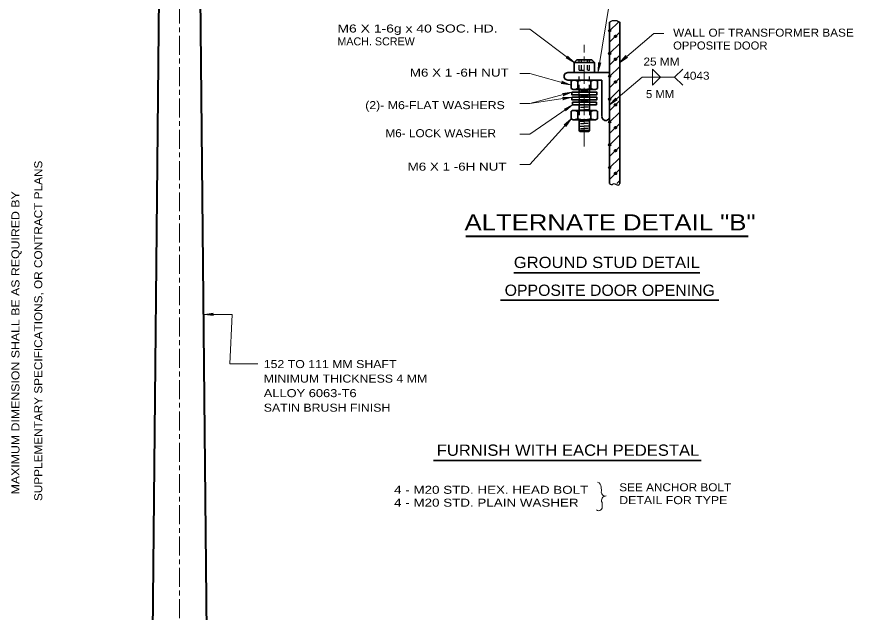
# Model space of a CAD drawing. Extents: x 312583 to 312854, y 144419 to 144597.
# Drawn here: x 312624.6 to 312704, y 144475.1 to 144531.6 of the extents above; entities that cross this region are included whole.
import ezdxf
from ezdxf.enums import TextEntityAlignment as Align

# ---------------------------------------------------------------- set-up
doc = ezdxf.new("R2010")
doc.units = 0
doc.header["$LTSCALE"] = 0.3
doc.header["$PDMODE"] = 32
doc.header["$PDSIZE"] = 0.15
doc.linetypes.add('LONG_DASH_SHORT_DASH', pattern=[9.9, 6, -1.2, 1.5, -1.2])
doc.linetypes.add('SHORT_DASHED', pattern=[2.7, 1.5, -1.2])
doc.layers.add('1', color=7, linetype='Continuous', lineweight=40)
doc.layers.add('2', color=7, linetype='Continuous', lineweight=13)

msp = doc.modelspace()

# ---------------------------------------------------------------- linework, layer by layer
at = {"layer": '1', "linetype": 'LONG_DASH_SHORT_DASH', "lineweight": 13}
for p, q in [((312640.0738, 144435.9326), (312640.0738, 144549.4913)), ((312678.4921, 144519.308), (312678.4921, 144528.9373))]:
    msp.add_line(p, q, dxfattribs=at)
at = {"layer": '1'}
for p, q in [((312638.2185, 144543.4576), (312637.4058, 144462.9576)), ((312641.9292, 144543.4576), (312642.7495, 144463.0189))]:
    msp.add_line(p, q, dxfattribs=at)
at = {"layer": '1', "lineweight": 35}
for p, q in [((312680.8918, 144515.7813), (312680.8918, 144531.1147)), ((312681.8501, 144515.7813), (312681.8501, 144531.1147)), ((312677.5338, 144526.323), (312677.5338, 144527.2813)), ((312679.2128, 144527.5267), (312679.4505, 144527.2813)), ((312680.8918, 144526.323), (312676.9358, 144526.323)), ((312680.1711, 144525.61), (312676.9358, 144525.61)), ((312677.2348, 144525.518), (312677.2348, 144524.7973)), ((312677.5108, 144525.61), (312678.4921, 144525.61)), ((312677.8635, 144525.518), (312677.8635, 144524.7973)), ((312679.4735, 144525.61), (312678.4921, 144525.61)), ((312679.1208, 144525.518), (312679.1208, 144524.7973)), ((312679.7495, 144525.518), (312679.7495, 144524.7973)), ((312680.1711, 144522.137), (312680.1711, 144525.61)), ((312677.5108, 144524.713), (312678.4921, 144524.713)), ((312678.0168, 144524.6977), (312678.0168, 144524.4523)), ((312679.4735, 144524.713), (312678.4921, 144524.713)), ((312678.9751, 144524.6977), (312678.9751, 144524.4523)), ((312678.0168, 144524.2147), (312678.0168, 144523.977)), ((312678.0168, 144523.7393), (312678.0168, 144523.5017)), ((312678.9751, 144524.2147), (312678.9751, 144523.977)), ((312678.9751, 144523.7393), (312678.9751, 144523.5017)), ((312678.0168, 144523.264), (312678.0168, 144522.735)), ((312678.9751, 144523.264), (312678.9751, 144522.735)), ((312677.2348, 144522.643), (312677.2348, 144521.9223)), ((312677.5108, 144522.735), (312678.4921, 144522.735)), ((312677.8635, 144522.643), (312677.8635, 144521.9223)), ((312679.4735, 144522.735), (312678.4921, 144522.735)), ((312679.1208, 144522.643), (312679.1208, 144521.9223)), ((312679.7495, 144522.643), (312679.7495, 144521.9223)), ((312677.5108, 144521.838), (312678.4921, 144521.838)), ((312678.0168, 144521.838), (312678.0168, 144520.8107)), ((312679.4735, 144521.838), (312678.4921, 144521.838)), ((312678.9751, 144521.838), (312678.9751, 144520.8107)), ((312678.0168, 144520.8107), (312678.4921, 144520.8107)), ((312678.9751, 144520.8107), (312678.4921, 144520.8107))]:
    msp.add_line(p, q, dxfattribs=at)
at = {"layer": '1', "lineweight": 13}
for p, q in [((312680.8918, 144530.2867), (312681.7275, 144531.1147)), ((312680.8918, 144529.198), (312681.8501, 144530.1563)), ((312680.8918, 144528.117), (312681.8501, 144529.0753)), ((312680.8918, 144527.0283), (312681.8501, 144527.9867)), ((312680.8841, 144525.9473), (312681.8501, 144526.9057)), ((312680.8918, 144524.8587), (312681.8501, 144525.8247)), ((312680.8918, 144523.7777), (312681.8501, 144524.736)), ((312680.8918, 144522.6967), (312681.8501, 144523.655)), ((312680.8918, 144521.608), (312681.8501, 144522.5663)), ((312680.8918, 144520.527), (312681.8501, 144521.4853)), ((312680.8918, 144519.4383), (312681.8501, 144520.4043)), ((312680.8918, 144518.3573), (312681.8501, 144519.3157)), ((312680.8918, 144517.2763), (312681.8501, 144518.2347)), ((312680.8918, 144516.1877), (312681.8501, 144517.146)), ((312681.5665, 144515.7813), (312681.8501, 144516.065)), ((312680.0905, 144486.9678), (312680.1212, 144486.6151)), ((312680.1749, 144485.5188), (312680.1749, 144485.2121))]:
    msp.add_line(p, q, dxfattribs=at)
at = {"layer": '1', "linetype": 'SHORT_DASHED', "lineweight": 25}
for p, q in [((312678.0168, 144526.5607), (312678.0168, 144527.5267)), ((312678.2161, 144526.5607), (312678.2161, 144527.5267)), ((312678.7911, 144526.5607), (312678.7911, 144527.5267)), ((312678.9751, 144526.5607), (312678.9751, 144527.5267)), ((312678.0168, 144526.5607), (312678.9751, 144526.5607)), ((312678.0168, 144524.6977), (312678.0168, 144526.323)), ((312678.9751, 144524.6977), (312678.9751, 144526.323)), ((312678.0168, 144524.2147), (312678.0168, 144524.4523)), ((312678.0168, 144523.977), (312678.0168, 144523.7393)), ((312678.9751, 144524.2147), (312678.9751, 144524.4523)), ((312678.9751, 144523.977), (312678.9751, 144523.7393)), ((312678.0168, 144523.5017), (312678.0168, 144523.264)), ((312678.9751, 144523.5017), (312678.9751, 144523.264)), ((312678.0168, 144522.735), (312678.0168, 144521.838)), ((312678.9751, 144522.735), (312678.9751, 144521.838))]:
    msp.add_line(p, q, dxfattribs=at)
at = {"layer": '1', "lineweight": 25}
for p, q in [((312678.1318, 144524.575), (312678.4921, 144524.575)), ((312678.8525, 144524.575), (312678.4921, 144524.575)), ((312678.1318, 144524.0997), (312678.4921, 144524.0997)), ((312678.1318, 144524.0997), (312678.8525, 144524.0997)), ((312678.8525, 144524.0997), (312678.4921, 144524.0997)), ((312678.1318, 144523.6167), (312678.8525, 144523.6167)), ((312678.1318, 144523.0263), (312678.4921, 144523.0263)), ((312678.8525, 144523.0263), (312678.4921, 144523.0263)), ((312678.0091, 144522.7887), (312678.4921, 144522.7887)), ((312678.9751, 144522.7887), (312678.4921, 144522.7887)), ((312678.0091, 144521.723), (312678.4921, 144521.723)), ((312678.1318, 144521.4853), (312678.4921, 144521.4853)), ((312678.9751, 144521.723), (312678.4921, 144521.723)), ((312678.8525, 144521.4853), (312678.4921, 144521.4853)), ((312678.0091, 144521.2477), (312678.4921, 144521.2477)), ((312678.1318, 144521.01), (312678.4921, 144521.01)), ((312678.9751, 144521.2477), (312678.4921, 144521.2477)), ((312678.8525, 144521.01), (312678.4921, 144521.01))]:
    msp.add_line(p, q, dxfattribs=at)
at = {"layer": '1', "lineweight": 35}
for points in [[(312679.2128, 144527.5267), (312677.7791, 144527.5267), (312677.5338, 144527.2813)], [(312679.4505, 144526.323), (312679.4505, 144527.2813), (312677.5338, 144527.2813)], [(312678.0168, 144520.8107), (312678.0781, 144520.7263), (312678.4921, 144520.7263)], [(312678.9751, 144520.8107), (312678.9138, 144520.7263), (312678.4921, 144520.7263)]]:
    msp.add_lwpolyline(points, dxfattribs=at)
for points in [[(312677.2961, 144524.4523), (312677.2961, 144524.2147), (312679.6958, 144524.2147), (312679.6958, 144524.4523)], [(312677.2961, 144523.977), (312677.2961, 144523.7393), (312679.6958, 144523.7393), (312679.6958, 144523.977)], [(312677.3575, 144523.5017), (312677.3575, 144523.264), (312679.6345, 144523.264), (312679.6345, 144523.5017)]]:
    msp.add_lwpolyline(points, close=True, dxfattribs=at)
for centre, radius, start, end in [((312676.9339, 144525.9646), 0.3584, 89.69361, 270.30639), ((312677.5259, 144525.0872), 0.5187, 91.66257, 124.1297), ((312677.2754, 144524.1529), 1.4854, 66.63635, 78.22986), ((312678.5583, 144522.9272), 2.6807, 91.405, 105.00202), ((312678.4269, 144522.9272), 2.6807, 74.99798, 88.595), ((312679.7099, 144524.1529), 1.4854, 101.77014, 113.36365), ((312679.4594, 144525.0872), 0.5187, 55.8703, 88.33743), ((312677.5259, 144525.2301), 0.5187, 235.8703, 268.33743), ((312677.2754, 144526.1643), 1.4854, 281.77014, 293.36365), ((312678.5583, 144527.3901), 2.6807, 254.99798, 268.595), ((312678.4269, 144527.3901), 2.6807, 271.405, 285.00202), ((312679.7099, 144526.1643), 1.4854, 246.63635, 258.22986), ((312679.4594, 144525.2301), 0.5187, 271.66257, 304.1297), ((312677.5259, 144522.2122), 0.5187, 91.66257, 124.1297), ((312677.2754, 144521.2779), 1.4854, 66.63635, 78.22986), ((312678.5583, 144520.0522), 2.6807, 91.405, 105.00202), ((312678.4269, 144520.0522), 2.6807, 74.99798, 88.595), ((312679.7099, 144521.2779), 1.4854, 101.77014, 113.36365), ((312679.4594, 144522.2122), 0.5187, 55.8703, 88.33743), ((312680.5295, 144522.1313), 0.3584, 179.69361, 0.30639), ((312677.5259, 144522.3551), 0.5187, 235.8703, 268.33743), ((312677.2754, 144523.2893), 1.4854, 281.77014, 293.36365), ((312678.5583, 144524.5151), 2.6807, 254.99798, 268.595), ((312678.4269, 144524.5151), 2.6807, 271.405, 285.00202), ((312679.7099, 144523.2893), 1.4854, 246.63635, 258.22986), ((312679.4594, 144522.3551), 0.5187, 271.66257, 304.1297)]:
    msp.add_arc(centre, radius, start, end, dxfattribs=at)
at = {"layer": '1', "lineweight": 13}
for centre, radius, start, end in [((312679.6671, 144487.0146), 0.4244, 353.39942, 80.7899), ((312680.4787, 144486.5106), 0.3751, 164.42602, 281.94122), ((312680.5526, 144485.717), 0.4266, 89.50519, 207.40776), ((312679.8467, 144485.0888), 0.3487, 232.68192, 20.20493)]:
    msp.add_arc(centre, radius, start, end, dxfattribs=at)
at = {"layer": '1', "lineweight": 25}
for points in [[(312680.8918, 144531.1147), (312681.0451, 144531.2143), (312681.3135, 144531.268), (312681.4898, 144531.268), (312681.8501, 144531.1147)], [(312680.8918, 144515.7813), (312681.1678, 144515.697), (312681.3135, 144515.789), (312681.5128, 144515.697), (312681.8348, 144515.697), (312681.8501, 144515.7813)]]:
    msp.add_spline(points, degree=3, dxfattribs=at)
at = {"layer": '1'}
for p in [(312680.9071, 144530.302), (312681.4515, 144529.7577), (312680.9071, 144528.1323), (312681.4515, 144527.588), (312680.9071, 144525.9627), (312681.4515, 144525.426), (312680.9071, 144523.8007), (312681.4515, 144523.2563), (312680.9071, 144521.631), (312681.4515, 144521.0867), (312680.9071, 144519.4613), (312681.4515, 144518.917), (312680.9071, 144517.2917), (312681.4515, 144516.7473)]:
    msp.add_point(p, dxfattribs=at)
at = {"layer": '2'}
for p, q in [((312679.8185, 144526.415), (312681.7198, 144538.1603)), ((312673.3248, 144530.4553), (312672.3665, 144530.4553)), ((312673.3248, 144530.4553), (312677.5338, 144527.2813)), ((312676.7825, 144527.7183), (312677.0661, 144527.6417)), ((312677.5338, 144527.2813), (312676.7825, 144527.7183)), ((312676.9051, 144527.887), (312677.0661, 144527.6417)), ((312677.5338, 144527.2813), (312676.9051, 144527.887)), ((312681.8501, 144527.2813), (312682.4405, 144527.9253)), ((312681.8501, 144527.2813), (312682.5785, 144527.7643)), ((312682.4405, 144527.9253), (312682.3025, 144527.6647)), ((312682.5785, 144527.7643), (312682.3025, 144527.6647)), ((312679.8185, 144526.415), (312679.8491, 144527.289)), ((312679.8185, 144526.415), (312680.0638, 144527.2583)), ((312679.8491, 144527.289), (312679.9181, 144526.9977)), ((312680.0638, 144527.2583), (312679.9181, 144526.9977)), ((312673.3248, 144526.231), (312672.3665, 144526.231)), ((312673.3248, 144526.231), (312677.1505, 144525.1653)), ((312687.8301, 144526.6527), (312687.0635, 144525.886)), ((312676.2841, 144525.2957), (312676.5831, 144525.3263)), ((312677.1505, 144525.1653), (312676.2841, 144525.2957)), ((312676.3455, 144525.5027), (312676.5831, 144525.3263)), ((312677.1505, 144525.1653), (312676.3455, 144525.5027)), ((312687.8301, 144525.1193), (312687.0635, 144525.886)), ((312673.3248, 144523.3713), (312677.2961, 144524.4523)), ((312673.3248, 144523.3713), (312677.2961, 144523.977)), ((312677.2961, 144523.977), (312676.4221, 144523.954)), ((312677.2961, 144523.977), (312676.4221, 144523.954)), ((312676.4221, 144523.954), (312676.7135, 144523.885)), ((312676.4221, 144523.954), (312676.7135, 144523.885)), ((312677.2961, 144524.4523), (312676.4375, 144524.3297)), ((312676.4375, 144524.3297), (312676.7288, 144524.299)), ((312677.2961, 144523.977), (312676.4605, 144523.7393)), ((312677.2961, 144523.977), (312676.4605, 144523.7393)), ((312676.4605, 144523.7393), (312676.7135, 144523.885)), ((312676.4605, 144523.7393), (312676.7135, 144523.885)), ((312677.2961, 144524.4523), (312676.4911, 144524.1227)), ((312676.4911, 144524.1227), (312676.7288, 144524.299)), ((312680.8918, 144523.2563), (312681.4821, 144523.9003)), ((312680.8918, 144523.2563), (312681.6201, 144523.7317)), ((312681.4821, 144523.9003), (312681.3365, 144523.6397)), ((312681.6201, 144523.7317), (312681.3365, 144523.6397)), ((312673.3248, 144523.3713), (312672.3665, 144523.3713)), ((312673.3248, 144520.481), (312677.3575, 144523.264)), ((312677.3575, 144523.264), (312676.5831, 144522.8577)), ((312676.5831, 144522.8577), (312676.8745, 144522.9267)), ((312677.3575, 144523.264), (312676.7058, 144522.6813)), ((312676.7058, 144522.6813), (312676.8745, 144522.9267)), ((312673.3248, 144517.583), (312677.2348, 144521.9223)), ((312677.2348, 144521.9223), (312676.5755, 144521.355)), ((312676.5755, 144521.355), (312676.8438, 144521.4853)), ((312677.2348, 144521.9223), (312676.7365, 144521.2093)), ((312676.7365, 144521.2093), (312676.8438, 144521.4853)), ((312673.3248, 144520.481), (312672.3665, 144520.481)), ((312673.3248, 144517.583), (312672.3665, 144517.583)), ((312642.4352, 144503.3686), (312643.3015, 144503.4759)), ((312642.4352, 144503.3686), (312643.3015, 144503.2613)), ((312645.0878, 144503.3686), (312642.4352, 144503.3686)), ((312643.3015, 144503.4759), (312643.0255, 144503.3686)), ((312643.3015, 144503.2613), (312643.0255, 144503.3686)), ((312645.0878, 144503.3686), (312644.8655, 144498.6843)), ((312647.5182, 144498.6843), (312644.8655, 144498.6843))]:
    msp.add_line(p, q, dxfattribs=at)
at = {"layer": '2', "lineweight": 40}
msp.add_line((312667.2516, 144510.807), (312694.0396, 144510.807), dxfattribs=at)
at = {"layer": '2', "lineweight": 35}
for p, q in [((312671.8056, 144507.3289), (312689.4506, 144507.3289)), ((312670.53, 144504.7203), (312691.2725, 144504.7203)), ((312689.5796, 144489.5189), (312664.1736, 144489.5189))]:
    msp.add_line(p, q, dxfattribs=at)
at = {"layer": '2'}
for points in [[(312681.8501, 144527.2813), (312685.0855, 144530.026), (312686.0438, 144530.026)], [(312684.9551, 144525.886), (312684.9551, 144526.6527), (312685.7218, 144525.886)], [(312680.8918, 144523.2563), (312683.9968, 144525.886), (312684.9551, 144525.886), (312687.0635, 144525.886)], [(312684.9551, 144525.886), (312684.9551, 144525.1193), (312685.7218, 144525.886)]]:
    msp.add_lwpolyline(points, dxfattribs=at)

# ---------------------------------------------------------------- texts
for s, width, p in [('M6 X 1-6g x 40 SOC. HD.', 1.3, (312655.0619, 144530.1209)), ('WALL OF TRANSFORMER BASE', 1.1, (312686.9226, 144529.728)), ('OPPOSITE DOOR', 1.05, (312686.9226, 144528.508)), ('25 MM', 1.1, (312684.1081, 144526.9832)), ('M6 X 1 -6H NUT', 1.25, (312661.9324, 144525.9367)), ('4043', 1.1, (312687.8893, 144525.6416)), ('5 MM', 1.05, (312684.3475, 144523.8994)), ('(2)- M6-FLAT WASHERS', 1.15, (312657.6991, 144522.849)), ('M6- LOCK WASHER', 1.1, (312659.6138, 144520.1867)), ('M6 X 1 -6H NUT', 1.25, (312661.7216, 144517.0128)), ('152 TO 111 MM SHAFT', 1.15, (312648.0702, 144498.2769)), ('MINIMUM THICKNESS 4 MM', 1.15, (312648.0702, 144496.8969)), ('ALLOY 6063-T6', 1.2, (312648.0702, 144495.5169)), ('SATIN BRUSH FINISH', 1.15, (312648.0702, 144494.1369)), ('SEE ANCHOR BOLT', 1.1, (312681.8079, 144486.5834)), ('4 - M20 STD. HEX. HEAD BOLT', 1.25, (312660.4423, 144486.3439)), ('4 - M20 STD. PLAIN WASHER', 1.25, (312660.4423, 144485.1239)), ('DETAIL FOR TYPE', 1.15, (312681.8079, 144485.3634))]:
    msp.add_text(s, height=0.76, dxfattribs=dict(at, width=width)).set_placement(p)
msp.add_text('MACH. SCREW', height=0.76, dxfattribs=at).set_placement((312655.0619, 144528.9009))
for s, width, p in [('SUPPLEMENTARY SPECIFICATIONS, OR CONTRACT PLANS', 1.1, (312627.0497, 144485.6573)), ('MAXIMUM DIMENSION SHALL BE AS REQUIRED BY', 1.15, (312624.8845, 144486.2884))]:
    msp.add_text(s, height=0.76, rotation=90, dxfattribs=dict(at, width=width)).set_placement(p)
for s, height, width, p in [('ALTERNATE DETAIL "B"', 1.52, 1.2, (312680.9354, 144511.3463)), ('GROUND STUD DETAIL', 1.07, 1.1, (312680.6322, 144507.7712)), ('OPPOSITE DOOR OPENING', 1.07, 1.05, (312680.9093, 144505.1264)), ('FURNISH WITH EACH PEDESTAL', 1.07, 1.1, (312676.9463, 144489.9516))]:
    msp.add_text(s, height=height, dxfattribs=dict(at, width=width)).set_placement(p, align=Align.CENTER)

doc.saveas('drawing.dxf')
